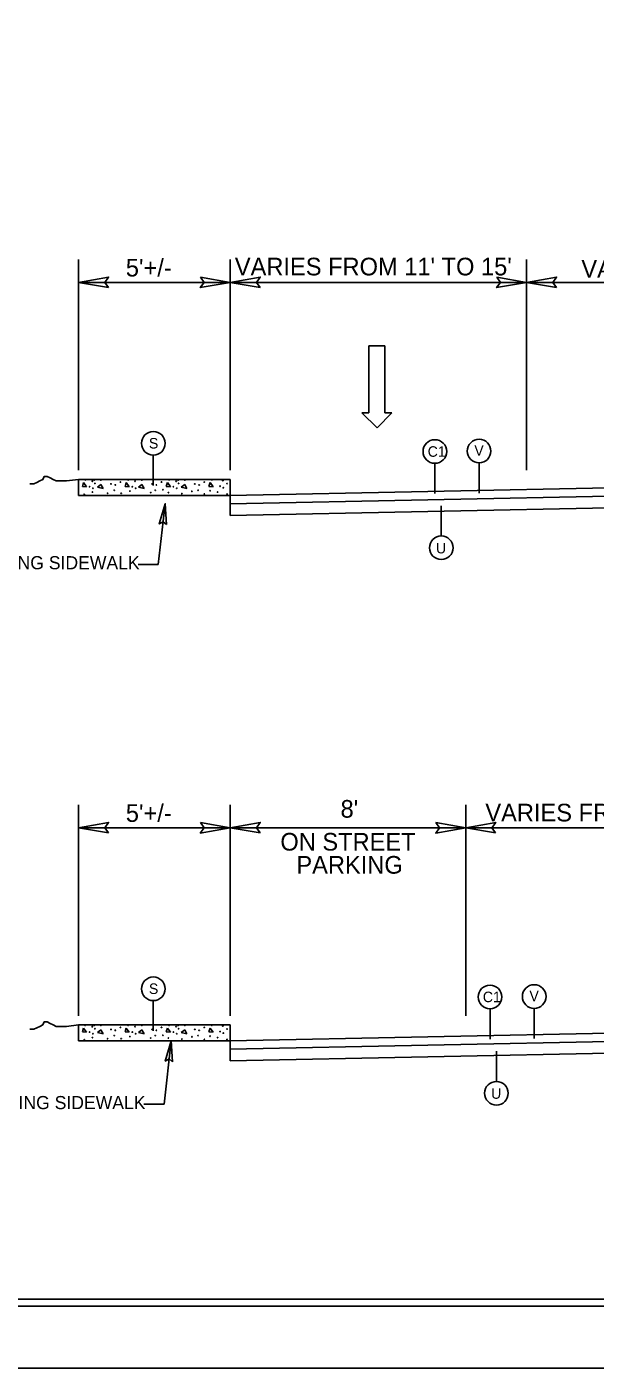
# Model space of a CAD drawing. Extents: x 1022283 to 1026986, y 174822 to 180471.
# Drawn here: x 1023116 to 1023630, y 177721 to 178936 of the extents above; entities that cross this region are included whole.
import ezdxf

# ---------------------------------------------------------------- set-up
doc = ezdxf.new("R2010")
doc.units = 0
for name, color, linetype in [('Default', 7, 'Continuous'), ('Prop Dimension', 7, 'Continuous'), ('Prop Lane Arrow CELL', 7, 'Continuous'), ('Prop Terminator CELL', 7, 'Continuous'), ('Sheet Cutting Line CELL', 7, 'Continuous'), ('Sheet Plot Border Inside CELL', 7, 'Continuous'), ('Sheet Plot Border Outside CELL', 7, 'Continuous'), ('Sheet Typical CELL', 7, 'Continuous'), ('Typical Curb CELL', 7, 'Continuous'), ('Typical ID Circle CELL', 7, 'Continuous'), ('Typical Slope Point Local CELL', 7, 'Continuous'), ('Typical Text General CELL', 7, 'Continuous'), ('Typical Text ID Circle CELL', 7, 'Continuous')]:
    doc.layers.add(name, color=color, linetype=linetype)

# ---------------------------------------------------------------- blocks, each defined once
blk = doc.blocks.new('Lane Arrow Through')
at = {"layer": 'Prop Lane Arrow CELL'}
for p, q in [((-3.15, 1.6), (-3.15, 3.1)), ((-3.15, 3.1), (0, 0)), ((-17.15, 1.6), (-3.15, 1.6)), ((-17.15, -1.7), (-17.15, 1.6)), ((0, 0), (-3.15, -3.2)), ((-3.15, -1.7), (-17.15, -1.7)), ((-3.15, -3.2), (-3.15, -1.7))]:
    blk.add_line(p, q, dxfattribs=at)
blk = doc.blocks.new('Terminator')
at = {"layer": 'Prop Terminator CELL'}
blk.add_lwpolyline([(-9, 1.55), (0, 0), (-9.05, -1.6), (-7.9, 0)], close=True, dxfattribs=at)

msp = doc.modelspace()

# ---------------------------------------------------------------- linework, layer by layer
at = {"layer": 'Default'}
for p, q in [((1023162.4, 178534.8), (1023162.4, 178725.6)), ((1023299.8, 178534.8), (1023299.8, 178725.6)), ((1023568, 178534.8), (1023568, 178725.6)), ((1023162.4, 178705), (1023299.8, 178705)), ((1023162.4, 178705), (1023299.8, 178705)), ((1023299.8, 178705), (1023807.5, 178705)), ((1023162.4, 178534.8), (1023162.4, 178690.8)), ((1023162.4, 178534.8), (1023162.4, 178690.8)), ((1023162.4, 178040.7), (1023162.4, 178231.6)), ((1023299.8, 178040.7), (1023299.8, 178231.6)), ((1023513, 178040.7), (1023513, 178231.6)), ((1023162.4, 178211), (1023299.8, 178211)), ((1023162.4, 178211), (1023299.8, 178211)), ((1023299.8, 178211), (1023807.5, 178211)), ((1023162.4, 178040.7), (1023162.4, 178196.8)), ((1023162.4, 178040.7), (1023162.4, 178196.8))]:
    msp.add_line(p, q, dxfattribs=at)
at = {"layer": 'Prop Dimension'}
for p, q in [((1023299.8, 178512), (1023807.5, 178522.1)), ((1023299.8, 178512), (1023807.5, 178522.1)), ((1023299.8, 178504.5), (1023807.5, 178514.6)), ((1023299.8, 178504.5), (1023807.5, 178514.6)), ((1023234.5, 178449.5), (1023240.9, 178504.5)), ((1023299.8, 178493.9), (1023807.5, 178504.1)), ((1023216.3, 178449.5), (1023234.5, 178449.5)), ((1023299.8, 178017.9), (1023807.5, 178028.1)), ((1023299.8, 178017.9), (1023807.5, 178028.1)), ((1023299.8, 178010.4), (1023807.5, 178020.6)), ((1023299.8, 178010.4), (1023807.5, 178020.6)), ((1023239.8, 177960.5), (1023246.4, 178017.9)), ((1023299.8, 177999.9), (1023807.5, 178010)), ((1023221.6, 177960.5), (1023239.8, 177960.5))]:
    msp.add_line(p, q, dxfattribs=at)
at = {"layer": 'Prop Terminator CELL'}
for points in [[(1023189.4, 178700.4), (1023162.4, 178705), (1023189.6, 178709.8), (1023186.1, 178705)], [(1023189.4, 178700.4), (1023162.4, 178705), (1023189.6, 178709.8), (1023186.1, 178705)], [(1023272.8, 178709.7), (1023299.8, 178705), (1023272.6, 178700.2), (1023276.1, 178705)], [(1023272.8, 178709.7), (1023299.8, 178705), (1023272.6, 178700.2), (1023276.1, 178705)], [(1023326.8, 178700.4), (1023299.8, 178705), (1023326.9, 178709.8), (1023323.5, 178705)], [(1023541, 178709.7), (1023568, 178705), (1023540.9, 178700.2), (1023544.3, 178705)], [(1023595, 178700.4), (1023568, 178705), (1023595.2, 178709.8), (1023591.7, 178705)], [(1023189.4, 178206.3), (1023162.4, 178211), (1023189.6, 178215.8), (1023186.1, 178211)], [(1023189.4, 178206.3), (1023162.4, 178211), (1023189.6, 178215.8), (1023186.1, 178211)], [(1023272.8, 178215.6), (1023299.8, 178211), (1023272.6, 178206.2), (1023276.1, 178211)], [(1023272.8, 178215.6), (1023299.8, 178211), (1023272.6, 178206.2), (1023276.1, 178211)], [(1023326.8, 178206.3), (1023299.8, 178211), (1023326.9, 178215.8), (1023323.5, 178211)], [(1023486, 178215.6), (1023513, 178211), (1023485.8, 178206.2), (1023489.3, 178211)], [(1023540, 178206.3), (1023513, 178211), (1023540.1, 178215.8), (1023536.7, 178211)]]:
    msp.add_lwpolyline(points, close=True, dxfattribs=at)
at = {"layer": 'Sheet Cutting Line CELL'}
msp.add_line((1022283.2, 177721.5), (1026493.2, 177721.5), dxfattribs=at)
at = {"layer": 'Sheet Plot Border Inside CELL'}
msp.add_lwpolyline([(1026482, 180415.4), (1022315.7, 180415.4), (1022315.7, 177777.6), (1026482, 177777.6)], close=True, dxfattribs=at)
at = {"layer": 'Sheet Plot Border Outside CELL'}
msp.add_lwpolyline([(1026493.2, 180471.5), (1022283.2, 180471.5), (1022283.2, 177721.5), (1026493.2, 177721.5)], close=True, dxfattribs=at)
at = {"layer": 'Sheet Typical CELL'}
msp.add_lwpolyline([(1026450.7, 180409), (1022700.7, 180409), (1022700.7, 177784), (1026450.7, 177784)], close=True, dxfattribs=at)
at = {"layer": 'Typical Curb CELL'}
for p, q in [((1023162.4, 178526.5), (1023299.8, 178526.5)), ((1023162.4, 178512), (1023162.4, 178526.5)), ((1023162.4, 178526.5), (1023299.8, 178526.5)), ((1023162.4, 178512), (1023162.4, 178526.5)), ((1023166.9, 178523.6), (1023165.9, 178520.1)), ((1023166.9, 178523.6), (1023165.9, 178520.1)), ((1023165.9, 178520.1), (1023169.6, 178519.9)), ((1023165.9, 178520.1), (1023169.6, 178519.9)), ((1023169.6, 178519.9), (1023166.9, 178523.6)), ((1023169.6, 178519.9), (1023166.9, 178523.6)), ((1023182.7, 178521.9), (1023179.5, 178519.5)), ((1023182.7, 178521.9), (1023179.5, 178519.5)), ((1023179.5, 178519.5), (1023184.6, 178518.3)), ((1023179.5, 178519.5), (1023184.6, 178518.3)), ((1023184.6, 178518.3), (1023182.7, 178521.9)), ((1023184.6, 178518.3), (1023182.7, 178521.9)), ((1023205.6, 178523.6), (1023204.6, 178520.1)), ((1023205.6, 178523.6), (1023204.6, 178520.1)), ((1023204.6, 178520.1), (1023208.3, 178519.9)), ((1023204.6, 178520.1), (1023208.3, 178519.9)), ((1023208.3, 178519.9), (1023205.6, 178523.6)), ((1023208.3, 178519.9), (1023205.6, 178523.6)), ((1023219.8, 178521.9), (1023216.6, 178519.5)), ((1023219.8, 178521.9), (1023216.6, 178519.5)), ((1023216.6, 178519.5), (1023221.8, 178518.3)), ((1023216.6, 178519.5), (1023221.8, 178518.3)), ((1023221.8, 178518.3), (1023219.8, 178521.9)), ((1023221.8, 178518.3), (1023219.8, 178521.9)), ((1023242.8, 178523.6), (1023241.7, 178520.1)), ((1023242.8, 178523.6), (1023241.7, 178520.1)), ((1023241.7, 178520.1), (1023245.5, 178519.9)), ((1023241.7, 178520.1), (1023245.5, 178519.9)), ((1023245.5, 178519.9), (1023242.8, 178523.6)), ((1023245.5, 178519.9), (1023242.8, 178523.6)), ((1023258.5, 178521.9), (1023255.3, 178519.5)), ((1023258.5, 178521.9), (1023255.3, 178519.5)), ((1023255.3, 178519.5), (1023260.5, 178518.3)), ((1023255.3, 178519.5), (1023260.5, 178518.3)), ((1023260.5, 178518.3), (1023258.5, 178521.9)), ((1023260.5, 178518.3), (1023258.5, 178521.9)), ((1023281.5, 178523.6), (1023280.5, 178520.1)), ((1023281.5, 178523.6), (1023280.5, 178520.1)), ((1023280.5, 178520.1), (1023284.2, 178519.9)), ((1023280.5, 178520.1), (1023284.2, 178519.9)), ((1023284.2, 178519.9), (1023281.5, 178523.6)), ((1023284.2, 178519.9), (1023281.5, 178523.6)), ((1023299.8, 178493.9), (1023299.8, 178526.5)), ((1023299.8, 178516.2), (1023299.8, 178526.5)), ((1023299.8, 178493.9), (1023299.8, 178526.5)), ((1023299.8, 178516.2), (1023299.8, 178526.5)), ((1023162.4, 178512), (1023299.8, 178512)), ((1023299.8, 178495.5), (1023299.8, 178513.5)), ((1023299.8, 178495.5), (1023299.8, 178513.5)), ((1023162.4, 178032.5), (1023299.8, 178032.5)), ((1023162.4, 178017.9), (1023162.4, 178032.5)), ((1023162.4, 178032.5), (1023299.8, 178032.5)), ((1023162.4, 178017.9), (1023162.4, 178032.5)), ((1023299.8, 177999.9), (1023299.8, 178032.5)), ((1023299.8, 178022.1), (1023299.8, 178032.5)), ((1023299.8, 177999.9), (1023299.8, 178032.5)), ((1023299.8, 178022.1), (1023299.8, 178032.5)), ((1023166.9, 178029.6), (1023165.9, 178026)), ((1023166.9, 178029.6), (1023165.9, 178026)), ((1023165.9, 178026), (1023169.6, 178025.8)), ((1023165.9, 178026), (1023169.6, 178025.8)), ((1023169.6, 178025.8), (1023166.9, 178029.6)), ((1023169.6, 178025.8), (1023166.9, 178029.6)), ((1023182.7, 178027.8), (1023179.5, 178025.5)), ((1023182.7, 178027.8), (1023179.5, 178025.5)), ((1023179.5, 178025.5), (1023184.6, 178024.3)), ((1023179.5, 178025.5), (1023184.6, 178024.3)), ((1023184.6, 178024.3), (1023182.7, 178027.8)), ((1023184.6, 178024.3), (1023182.7, 178027.8)), ((1023205.6, 178029.6), (1023204.6, 178026)), ((1023205.6, 178029.6), (1023204.6, 178026)), ((1023204.6, 178026), (1023208.3, 178025.8)), ((1023204.6, 178026), (1023208.3, 178025.8)), ((1023208.3, 178025.8), (1023205.6, 178029.6)), ((1023208.3, 178025.8), (1023205.6, 178029.6)), ((1023219.8, 178027.8), (1023216.6, 178025.5)), ((1023219.8, 178027.8), (1023216.6, 178025.5)), ((1023216.6, 178025.5), (1023221.8, 178024.3)), ((1023216.6, 178025.5), (1023221.8, 178024.3)), ((1023221.8, 178024.3), (1023219.8, 178027.8)), ((1023221.8, 178024.3), (1023219.8, 178027.8)), ((1023242.8, 178029.6), (1023241.7, 178026)), ((1023242.8, 178029.6), (1023241.7, 178026)), ((1023241.7, 178026), (1023245.5, 178025.8)), ((1023241.7, 178026), (1023245.5, 178025.8)), ((1023245.5, 178025.8), (1023242.8, 178029.6)), ((1023245.5, 178025.8), (1023242.8, 178029.6)), ((1023258.5, 178027.8), (1023255.3, 178025.5)), ((1023258.5, 178027.8), (1023255.3, 178025.5)), ((1023255.3, 178025.5), (1023260.5, 178024.3)), ((1023255.3, 178025.5), (1023260.5, 178024.3)), ((1023260.5, 178024.3), (1023258.5, 178027.8)), ((1023260.5, 178024.3), (1023258.5, 178027.8)), ((1023281.5, 178029.6), (1023280.5, 178026)), ((1023281.5, 178029.6), (1023280.5, 178026)), ((1023280.5, 178026), (1023284.2, 178025.8)), ((1023280.5, 178026), (1023284.2, 178025.8)), ((1023284.2, 178025.8), (1023281.5, 178029.6)), ((1023284.2, 178025.8), (1023281.5, 178029.6)), ((1023299.8, 178001.5), (1023299.8, 178019.4)), ((1023299.8, 178001.5), (1023299.8, 178019.4)), ((1023162.4, 178017.9), (1023299.8, 178017.9))]:
    msp.add_line(p, q, dxfattribs=at)
for centre in [(1023168.5, 178526.1), (1023168.5, 178526.1), (1023172.4, 178519.9), (1023172.4, 178519.9), (1023174.9, 178524.9), (1023174.9, 178524.9), (1023175.4, 178518.5), (1023175.4, 178518.5), (1023176.6, 178525.9), (1023176.6, 178525.9), (1023177.2, 178522.9), (1023177.2, 178522.9), (1023182.6, 178525.9), (1023182.6, 178525.9), (1023191.8, 178522.4), (1023191.8, 178522.4), (1023195.7, 178521.5), (1023195.7, 178521.5), (1023200.3, 178524.1), (1023200.3, 178524.1), (1023207.3, 178526.1), (1023207.3, 178526.1), (1023211.1, 178519.9), (1023211.1, 178519.9), (1023213.6, 178524.9), (1023213.6, 178524.9), (1023214.1, 178518.5), (1023214.1, 178518.5), (1023219.8, 178525.9), (1023219.8, 178525.9), (1023229, 178522.4), (1023229, 178522.4), (1023232.9, 178521.5), (1023232.9, 178521.5), (1023237.5, 178524.1), (1023237.5, 178524.1), (1023238.8, 178517.1), (1023238.8, 178517.1), (1023244.4, 178526.1), (1023244.4, 178526.1), (1023248.3, 178519.9), (1023248.3, 178519.9), (1023250.8, 178524.9), (1023250.8, 178524.9), (1023251.3, 178518.5), (1023251.3, 178518.5), (1023252.5, 178525.9), (1023252.5, 178525.9), (1023253, 178522.9), (1023253, 178522.9), (1023258.5, 178525.9), (1023258.5, 178525.9), (1023267.7, 178522.4), (1023267.7, 178522.4), (1023271.6, 178521.5), (1023271.6, 178521.5), (1023276.2, 178524.1), (1023276.2, 178524.1), (1023283.1, 178526.1), (1023283.1, 178526.1), (1023290.5, 178520.4), (1023290.5, 178520.4), (1023293, 178525.4), (1023293, 178525.4), (1023293.5, 178519), (1023293.5, 178519), (1023296.9, 178522.7), (1023296.9, 178522.7), (1023167.6, 178513), (1023167.6, 178513), (1023175, 178515), (1023175, 178515), (1023188.7, 178514), (1023188.7, 178514), (1023194.7, 178516.7), (1023194.7, 178516.7), (1023201, 178514), (1023201, 178514), (1023208.9, 178515.9), (1023208.9, 178515.9), (1023227.8, 178514.6), (1023227.8, 178514.6), (1023231.8, 178516.7), (1023231.8, 178516.7), (1023243.8, 178514.6), (1023243.8, 178514.6), (1023256, 178513.6), (1023256, 178513.6), (1023265, 178515.7), (1023265, 178515.7), (1023270.6, 178516.7), (1023270.6, 178516.7), (1023276.4, 178513.3), (1023276.4, 178513.3), (1023281.5, 178516.2), (1023281.5, 178516.2), (1023288.3, 178515), (1023288.3, 178515), (1023296.9, 178513.2), (1023296.9, 178513.2), (1023168.5, 178032), (1023168.5, 178032), (1023176.6, 178031.9), (1023176.6, 178031.9), (1023182.6, 178031.9), (1023182.6, 178031.9), (1023207.3, 178032), (1023207.3, 178032), (1023219.8, 178031.9), (1023219.8, 178031.9), (1023244.4, 178032), (1023244.4, 178032), (1023252.5, 178031.9), (1023252.5, 178031.9), (1023258.5, 178031.9), (1023258.5, 178031.9), (1023283.1, 178032), (1023283.1, 178032), (1023293, 178031.4), (1023293, 178031.4), (1023167.6, 178019), (1023167.6, 178019), (1023172.4, 178025.9), (1023172.4, 178025.9), (1023174.9, 178030.8), (1023174.9, 178030.8), (1023175, 178020.9), (1023175, 178020.9), (1023175.4, 178024.4), (1023175.4, 178024.4), (1023177.2, 178028.9), (1023177.2, 178028.9), (1023188.7, 178019.9), (1023188.7, 178019.9), (1023191.8, 178028.3), (1023191.8, 178028.3), (1023194.7, 178022.7), (1023194.7, 178022.7), (1023195.7, 178027.5), (1023195.7, 178027.5), (1023200.3, 178030.1), (1023200.3, 178030.1), (1023201, 178019.9), (1023201, 178019.9), (1023208.9, 178021.8), (1023208.9, 178021.8), (1023211.1, 178025.9), (1023211.1, 178025.9), (1023213.6, 178030.8), (1023213.6, 178030.8), (1023214.1, 178024.4), (1023214.1, 178024.4), (1023227.8, 178020.5), (1023227.8, 178020.5), (1023229, 178028.3), (1023229, 178028.3), (1023231.8, 178022.7), (1023231.8, 178022.7), (1023232.9, 178027.5), (1023232.9, 178027.5), (1023237.5, 178030.1), (1023237.5, 178030.1), (1023238.8, 178023), (1023238.8, 178023), (1023243.8, 178020.5), (1023243.8, 178020.5), (1023248.3, 178025.9), (1023248.3, 178025.9), (1023250.8, 178030.8), (1023250.8, 178030.8), (1023251.3, 178024.4), (1023251.3, 178024.4), (1023253, 178028.9), (1023253, 178028.9), (1023256, 178019.6), (1023256, 178019.6), (1023265, 178021.6), (1023265, 178021.6), (1023267.7, 178028.3), (1023267.7, 178028.3), (1023270.6, 178022.7), (1023270.6, 178022.7), (1023271.6, 178027.5), (1023271.6, 178027.5), (1023276.2, 178030.1), (1023276.2, 178030.1), (1023276.4, 178019.3), (1023276.4, 178019.3), (1023281.5, 178022.2), (1023281.5, 178022.2), (1023288.3, 178020.9), (1023288.3, 178020.9), (1023290.5, 178026.4), (1023290.5, 178026.4), (1023293.5, 178025), (1023293.5, 178025), (1023296.9, 178028.7), (1023296.9, 178028.7), (1023296.9, 178019.2), (1023296.9, 178019.2)]:
    msp.add_circle(centre, 0.249, dxfattribs=at)
at = {"layer": 'Typical ID Circle CELL'}
for p, q in [((1023230.1, 178548.5), (1023230.1, 178521)), ((1023525, 178541.5), (1023525, 178514)), ((1023485, 178541.1), (1023485, 178513.6)), ((1023490.8, 178475.2), (1023490.8, 178502.7)), ((1023230.1, 178054.5), (1023230.1, 178027)), ((1023534.9, 178047.1), (1023534.9, 178019.6)), ((1023574.9, 178047.5), (1023574.9, 178020)), ((1023540.7, 177981.2), (1023540.7, 178008.7))]:
    msp.add_line(p, q, dxfattribs=at)
for centre in [(1023230.1, 178559.2), (1023485, 178551.8), (1023525, 178552.2), (1023490.8, 178464.6), (1023230.1, 178065.1), (1023534.9, 178057.7), (1023574.9, 178058.1), (1023540.7, 177970.5)]:
    msp.add_circle(centre, 10.7, dxfattribs=at)
at = {"layer": 'Typical Slope Point Local CELL'}
for points in [[(1023162.4, 178526.5), (1023151.6, 178525.2), (1023149, 178525.2), (1023144.9, 178525.2), (1023142.2, 178525.2), (1023139.5, 178526.5), (1023136.8, 178527.9), (1023134.1, 178529.2), (1023131.4, 178529.2), (1023130.1, 178526.5), (1023127.4, 178525.2), (1023124.7, 178523.8), (1023122, 178522.5), (1023119.3, 178522.5), (1023118.3, 178522.5)], [(1023162.4, 178526.5), (1023151.6, 178525.2), (1023149, 178525.2), (1023144.9, 178525.2), (1023142.2, 178525.2), (1023139.5, 178526.5), (1023136.8, 178527.9), (1023134.1, 178529.2), (1023131.4, 178529.2), (1023130.1, 178526.5), (1023127.4, 178525.2), (1023124.7, 178523.8), (1023122, 178522.5), (1023119.3, 178522.5), (1023118.3, 178522.5)], [(1023162.4, 178032.5), (1023151.6, 178031.1), (1023149, 178031.1), (1023144.9, 178031.1), (1023142.2, 178031.1), (1023139.5, 178032.5), (1023136.8, 178033.8), (1023134.1, 178035.2), (1023131.4, 178035.2), (1023130.1, 178032.5), (1023127.4, 178031.1), (1023124.7, 178029.8), (1023122, 178028.4), (1023119.3, 178028.4), (1023118.3, 178028.4)], [(1023162.4, 178032.5), (1023151.6, 178031.1), (1023149, 178031.1), (1023144.9, 178031.1), (1023142.2, 178031.1), (1023139.5, 178032.5), (1023136.8, 178033.8), (1023134.1, 178035.2), (1023131.4, 178035.2), (1023130.1, 178032.5), (1023127.4, 178031.1), (1023124.7, 178029.8), (1023122, 178028.4), (1023119.3, 178028.4), (1023118.3, 178028.4)]]:
    msp.add_lwpolyline(points, dxfattribs=at)

# ---------------------------------------------------------------- block references
at = {"layer": 'Prop Dimension', "xscale": 2.0767499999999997, "yscale": -2.076749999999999, "rotation": 83.4116733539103}
for p in [(1023240.9, 178504.5), (1023246.4, 178017.9)]:
    msp.add_blockref('Terminator', p, dxfattribs=at)
at = {"layer": 'Prop Lane Arrow CELL', "xscale": 4.329849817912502, "yscale": 4.3298498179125, "rotation": -89.99999999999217}
msp.add_blockref('Lane Arrow Through', (1023432.7, 178573.3), dxfattribs=at)

# ---------------------------------------------------------------- texts
at = {"layer": 'Prop Dimension'}
for s, p in [("5'+/-", (1023205.2, 178710.3)), ("VARIES FROM 11' TO 15'", (1023303.9, 178711.3)), ('VARIES FROM', (1023617.6, 178709.3)), ("5'+/-", (1023205.2, 178216.3)), ("8'", (1023399.6, 178220.1)), ("VARIES FROM 12' TO 14'", (1023530.7, 178216.7)), ('ON STREET', (1023345.1, 178190.3)), ('PARKING', (1023359.6, 178169.4))]:
    msp.add_text(s, height=16, dxfattribs=at).set_placement(p)
at = {"layer": 'Typical Text General CELL'}
for p in [(1023056.8, 178445.1), (1023062.1, 177956.1)]:
    msp.add_text('EXISTING SIDEWALK', height=11.898, dxfattribs=at).set_placement(p)
at = {"layer": 'Typical Text ID Circle CELL'}
for s, p in [('S', (1023226.1, 178554.5)), ('C1', (1023478.5, 178547)), ('V', (1023520.7, 178547.9)), ('U', (1023486, 178459.5)), ('S', (1023226.1, 178060.4)), ('C1', (1023528.4, 178053)), ('V', (1023570.6, 178053.8)), ('U', (1023535.9, 177965.5))]:
    msp.add_text(s, height=9.53, dxfattribs=at).set_placement(p)

doc.saveas('drawing.dxf')
